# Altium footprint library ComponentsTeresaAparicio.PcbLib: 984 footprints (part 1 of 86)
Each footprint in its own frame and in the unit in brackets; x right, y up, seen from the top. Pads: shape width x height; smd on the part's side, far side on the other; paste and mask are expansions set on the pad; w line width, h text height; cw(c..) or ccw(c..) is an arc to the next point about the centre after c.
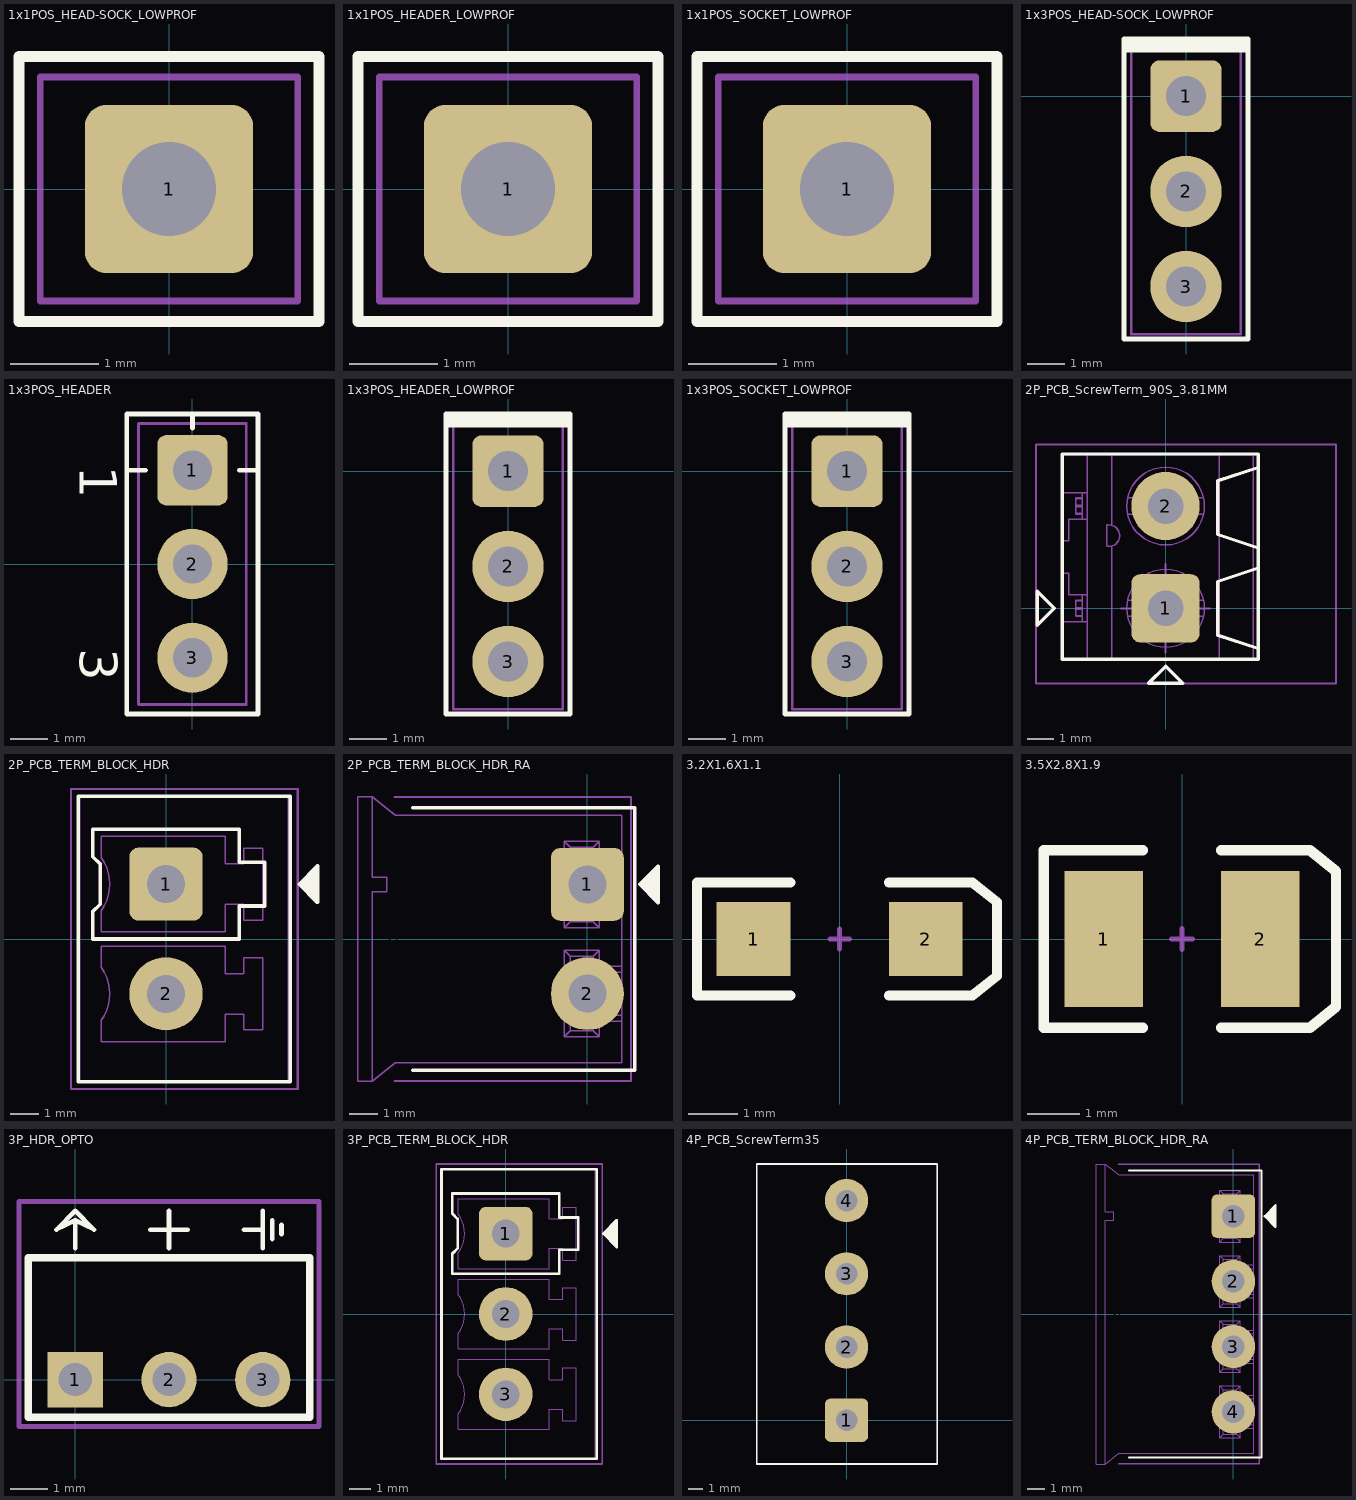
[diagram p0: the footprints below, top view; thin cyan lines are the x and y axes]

## 1x1POS_HEAD-SOCK_LOWPROF [mil] "Connector Socket with header, Single-row 1-position, 0.100\" pitch"
height 290
pads (1):
  rrect25% 75x75 hole 42: 1(0,0)
Top Overlay:
  lines w5: -66.93,-59.05 66.93,-59.05 66.93,59.06 -66.93,59.06 -66.93,-59.05
Mechanical 13:
  lines w3: -57.47,-49.99 57.49,-49.99 57.49,50.01 -57.47,50.01 -57.47,-49.99
3D body: height 165, standoff -125, extent -57.47,-50 57.49,50
3D body: height 408, standoff 23, extent -57.47,-50 57.49,50

## 1x1POS_HEADER_LOWPROF [mil] "Connector Header, Single-row 1-position, 0.100\" pitch"
height 267
pads (1):
  rrect25% 75x75 hole 42: 1(0,0)
Top Overlay:
  lines w5: -66.93,-59.06 66.93,-59.06 66.93,59.06 -66.93,59.06 -66.93,-59.06
Mechanical 13:
  lines w3: -57.47,-50 57.49,-50 57.49,50 -57.47,50 -57.47,-50
3D body: height 267, standoff -118, extent -57.47,-50 57.49,50

## 1x1POS_SOCKET_LOWPROF [mil] "Connector Socket, Single-row 1-position, 0.100\" pitch"
height 165
pads (1):
  rrect25% 75x75 hole 42: 1(0,0)
Top Overlay:
  lines w5: -66.93,-59.06 -66.93,59.06 66.93,59.06 66.93,-59.06 -66.93,-59.06
Mechanical 13:
  lines w3: -57.47,-50 -57.47,50 57.49,50 57.49,-50 -57.47,-50
3D body: height 165, standoff -125, extent -57.47,-50 57.49,50

## 1x3POS_HEAD-SOCK_LOWPROF [mil] "Connector Socket with header, Single-row 3-position, 0.100\" pitch"
height 290
pads (3):
  rrect25% 75x75 hole 42: 1(0,0)
  round 75 hole 42: 2(0,-100) 3(0,-200)
Top Overlay:
  lines w5: -65,48.19 65,48.19 ; -65,52.13 65,52.13 ; -65,56.06 65,56.06 ; -65,-255 -65,60 65,60 65,-255 -65,-255
Mechanical 13:
  lines w3: -57.47,-250 -57.47,50 57.49,50 57.49,-250 -57.47,-250
3D body: height 165, standoff -125, extent -57.47,-50 57.49,50
3D body: height 165, standoff -125, extent -57.47,-150 57.49,-50
3D body: height 165, standoff -125, extent -57.47,-250 57.49,-150
3D body: height 408, standoff 23, extent -57.48,-50 57.49,50
3D body: height 408, standoff 23, extent -57.48,-150 57.49,-50
3D body: height 408, standoff 23, extent -57.48,-250 57.49,-150

## 1x3POS_HEADER [mil] "Connector Header, Single-row 3-position, 0.100\" pitch"
height 235
pads (3):
  rrect25% 75x75 hole 42: 1(0,100)
  round 75 hole 42: 2(0,0) 3(0,-100)
Top Overlay:
  lines w5: -70,100 -50,100 ; 0,145 0,160 ; 50,100 70,100 ; -70,-160 70,-160 70,160 -70,160 -70,-160
  text "1" at -120,105 h40
  text "3" at -120,-90 h40
Mechanical 13:
  lines w3: -57.47,-150 57.49,-150 57.49,150 -57.47,150 -57.47,-150
3D body: height 335.04, standoff -144.88, extent -57.47,-150 57.49,150

## 1x3POS_HEADER_LOWPROF [mil] "Connector Header, Single-row 3-position, 0.100\" pitch"
height 267
pads (3):
  rrect25% 75x75 hole 42: 1(0,0)
  round 75 hole 42: 2(0,-100) 3(0,-200)
Top Overlay:
  lines w5: -65,48.19 65,48.19 ; -65,52.13 65,52.13 ; -65,56.06 65,56.06 ; -65,-255 65,-255 65,60 -65,60 -65,-255
Mechanical 13:
  lines w3: -57.47,-250 57.49,-250 57.49,50 -57.47,50 -57.47,-250
3D body: height 267, standoff -118, extent -57.47,-250 57.49,-150
3D body: height 267, standoff -118, extent -57.47,-150 57.49,-50
3D body: height 267, standoff -118, extent -57.47,-50 57.49,50

## 1x3POS_SOCKET_LOWPROF [mil] "Connector Socket, Single-row 3-position, 0.100\" pitch"
height 165
pads (3):
  rrect25% 75x75 hole 42: 1(0,0)
  round 75 hole 42: 2(0,-100) 3(0,-200)
Top Overlay:
  lines w5: -65,48.19 65,48.19 ; -65,52.13 65,52.13 ; -65,56.06 65,56.06 ; -65,-255 65,-255 65,60 -65,60 -65,-255
Mechanical 13:
  lines w3: -57.47,-250 57.49,-250 57.49,50 -57.47,50 -57.47,-250
3D body: height 165, standoff -125, extent -57.47,-250 57.49,-150
3D body: height 165, standoff -125, extent -57.47,-150 57.49,-50
3D body: height 165, standoff -125, extent -57.47,-50 57.49,50

## 2P_PCB_ScrewTerm_90S_3.81MM [mil] "TERM BLOCK 2POS SIDE ENT STACKABLE 3.81MM"
height 334.65
pads (2):
  rrect25% 100x100 hole 52: 1(0,0)
  round 100 hole 52: 2(0,150)
Top Overlay:
  lines w5: 135.83,-59.06 76.78,-39.37 76.78,39.37 135.83,59.06 ; 135.83,88.58 76.78,108.27 76.78,187.01 135.83,206.69 ; -188,-25 -163,0 -188,25 -188,-25 ; -151.57,-75 -151.57,226.38 135.83,226.38 135.83,-75 -151.57,-75 ; -25,-110 25,-110 0,-85 -25,-110
Mechanical 13:
  circle w1.97: c0,0 r57.09
  circle w1.97: c0,150 r57.09
  lines w1.97: -151.57,-19.69 -114.76,-19.69 -114.76,19.68 -141.73,19.68 -141.73,51.18 -151.57,51.18 ; -151.57,98.82 -141.73,98.82 -141.73,130.31 -114.76,130.31 -114.76,169.69 -151.57,169.69 ; -131.89,-10.91 -122.05,-10.91 ; -131.89,-1.06 -122.05,-1.06 ; -131.89,1.06 -122.05,1.06 ; -131.89,10.91 -122.05,10.91 ; -131.89,139.09 -122.05,139.09 ; -131.89,148.94 -122.05,148.94 ; -131.89,151.06 -122.05,151.06 ; -131.89,160.91 -122.05,160.91 ; -122.05,-19.69 -122.05,19.68 ; -122.05,-11.81 -131.89,-11.81 -131.89,11.81 -122.05,11.81 ; -122.05,130.31 -122.05,169.69 ; -122.05,138.19 -131.89,138.19 -131.89,161.81 -122.05,161.81 ; -114.56,-75 -114.56,225 ; -78.74,-75 -78.74,91.34 ; -78.74,121.65 -78.74,225 ; -55.85,-11.81 55.85,-11.81 ; -55.85,11.81 55.85,11.81 ; -55.85,138.19 55.85,138.19 ; -55.85,161.81 55.85,161.81 ; 78.74,-75 78.74,225 ; 128.89,-75 128.89,225 ; -151.57,-75 -151.57,225 135.83,225 135.83,-75 -151.57,-75 ; -85.91,90.75 -83.03,90.75 ccw(c-83.03,106.5) -83.03,122.24 -85.91,122.24 -85.91,90.75
Mechanical 14:
  lines w3: -65,0 65,0 ; 0,-65 0,65 ; -190,-110 -190,240 250,240 250,-110 -190,-110
3D body: height 334.65, standoff -137.8, extent -151.57,-75.19 135.83,224.81

## 2P_PCB_TERM_BLOCK_HDR [mil] "TERM BLOCK HDR 2POS 3.81MM"
height 362.2
pads (2):
  rrect25% 100x100 hole 52: 1(0,75)
  round 100 hole 52: 2(0,-75)
Top Overlay:
  region: 182,75 207,100 207,50
  lines w5: -120,-195.08 -120,195.08 ; -120,-195 170,-195 ; -120,195 170,195 ; 170,-195.08 170,195.08 ; -100,0 100,0 100,45 135,45 135,105 100,105 100,150 -100,150 -100,112.5 -90,102.5 -90,47.5 -100,37.5 -100,0 ; 182,75 207,100 207,50 182,75
Mechanical 13:
  circle w1.97: c0,-75 r43.31
  circle w1.97: c0,75 r43.31
  circle w1.97: c0,75 r35.43
  circle w1.97: c0,-75 r35.43
  lines w1.97: -118.11,-195.08 -118.11,195.08 167.32,195.08 167.32,-195.08 -118.11,-195.08 ; -88.58,-140.16 -88.58,-111.08 ccw(c-137.8,-75) -88.58,-38.92 -88.58,-9.84 80.71,-9.84 80.71,-47.44 106.3,-47.44 106.3,-25.79 131.89,-25.79 131.89,-124.21 106.3,-124.21 106.3,-102.56 80.71,-102.56 80.71,-140.16 -88.58,-140.16 ; -88.58,9.84 -88.58,38.92 ccw(c-137.8,75) -88.58,111.08 -88.58,140.16 80.71,140.16 80.71,102.56 106.3,102.56 106.3,124.21 131.89,124.21 131.89,25.79 106.3,25.79 106.3,47.44 80.71,47.44 80.71,9.84 -88.58,9.84 ; -15.75,-90.75 15.75,-90.75 15.75,-59.25 -15.75,-59.25 -15.75,-90.75 ; -15.75,59.25 15.75,59.25 15.75,90.75 -15.75,90.75 -15.75,59.25
Mechanical 14:
  lines w3: -130,-205 180,-205 180,205 -130,205 -130,-205
3D body: height 362.2, standoff -133.86, extent -118.1,-195.07 167.33,195.08

## 2P_PCB_TERM_BLOCK_HDR_RA [mil] "TERM BLOCK HDR 2POS 3.81MM RIGHT-ANGLE"
height 362.2
pads (3):
  round 40 on Mech14: 0(-265,0)
  rrect25% 100x100 hole 52: 1(0,75)
  round 100 hole 52: 2(0,-75)
Top Overlay:
  region: 72,75 97,100 97,50
  lines w5: -240,-180 65,-180 65,180 -240,180 ; 72,75 97,100 97,50 72,75
Mechanical 13:
  lines w1.97: 47.24,-112.8 7.87,-112.8 ; 47.24,-104.53 16.14,-104.53 ; 47.24,-45.47 16.14,-45.47 ; 47.24,-37.2 7.87,-37.2 ; 47.24,37.2 7.87,37.2 ; 47.24,45.47 16.14,45.47 ; 47.24,104.53 16.14,104.53 ; 47.24,112.8 7.87,112.8 ; -295.28,-195.08 -263.78,-169.88 47.24,-169.88 47.24,169.88 -263.78,169.88 -295.28,195.08 ; -295.28,-195.08 -314.96,-195.08 -314.96,195.08 -295.28,195.08 ; -295.28,-195.08 -295.28,65.16 -275.59,65.16 -275.59,84.84 -295.28,84.84 -295.28,195.08 ; -31.89,-134.45 -23.62,-126.18 ; -31.89,-134.45 16.14,-134.45 ; -31.89,-134.45 -31.89,-15.55 ; -31.89,-15.55 -23.62,-23.82 ; -31.89,-15.55 16.14,-15.55 ; -31.89,15.55 -23.62,23.82 ; -31.89,15.55 16.14,15.55 ; -31.89,15.55 -31.89,134.45 ; -31.89,134.45 -23.62,126.18 ; -31.89,134.45 16.14,134.45 ; -23.62,-126.18 7.87,-126.18 ; -23.62,-126.18 -23.62,-23.82 ; -23.62,-23.82 7.87,-23.82 ; -23.62,23.82 7.87,23.82 ; -23.62,23.82 -23.62,126.18 ; -23.62,126.18 7.87,126.18 ; 7.87,-126.18 7.87,-112.8 ; 7.87,-126.18 16.14,-134.45 ; 7.87,-112.8 cw(c16.14,-112.8) 16.14,-104.53 ; 7.87,-37.2 ccw(c16.14,-37.2) 16.14,-45.47 ; 7.87,-37.2 7.87,-23.82 ; 7.87,-23.82 16.14,-15.55 ; 7.87,23.82 7.87,37.2 ; 7.87,23.82 16.14,15.55 ; 7.87,37.2 cw(c16.14,37.2) 16.14,45.47 ; 7.87,112.8 ccw(c16.14,112.8) 16.14,104.53 ; 7.87,112.8 7.87,126.18 ; 7.87,126.18 16.14,134.45 ; 16.14,-134.45 16.14,-104.53 ; 16.14,-45.47 16.14,-15.55 ; 16.14,15.55 16.14,45.47 ; 16.14,104.53 16.14,134.45
Mechanical 14:
  lines w3: -265,-195 60,-195 60,195 -265,195
3D body: height 291.34, standoff -129.92, extent -314.95,-195.07 47.25,195.08

## 3.2X1.6X1.1 [mm] "SMT LED; 2 Flat Leads"
height 1.2
pads (2):
  rect 1.5x1.5 smd: 1(-1.75,0) 2(1.75,0)
Top Overlay:
  lines w0.2: -1,-1.15 -2.9,-1.15 -2.9,1.15 -1,1.15 ; 1,-1.15 2.7,-1.15 3.2,-0.75 3.2,0.75 2.7,1.15 1,1.15
Mechanical 1:
  lines w0.1: -0.2,0 0.2,0 ; 0,-0.2 0,0.2

## 3.5X2.8X1.9 [mm] "SM LED; 2 C-Bend Leads; Body 3.5 x 2.8 x 1.9 mm, inc leads (LxWxH typ)"
height 1.9
pads (2):
  rect 1.5x2.6 smd: 1(-1.5,0) 2(1.5,0)
Top Overlay:
  lines w0.2: -0.75,-1.7 -2.65,-1.7 -2.65,1.7 -0.75,1.7 ; 0.75,-1.7 2.45,-1.7 2.95,-1.3 2.95,1.3 2.45,1.7 0.75,1.7
Mechanical 1:
  lines w0.1: -0.2,0 0.2,0 ; 0,-0.2 0,0.2

## 3P_HDR_OPTO [mm] "Connector; screwterm; 3 Position"
height 10
pads (3):
  rect 1.5x1.5 hole 0.9: 1(0,0)
  round 1.5 hole 0.9: 2(2.54,0) 3(5.08,0)
Top Overlay:
  lines w0.127: 0,3.556 0,4.318 ; 2.032,4.064 3.048,4.064 ; 2.54,3.556 2.54,4.572 ; 4.572,4.064 5.08,4.064 5.08,4.572 5.08,3.556 ; 5.334,3.81 5.334,4.318 ; 5.588,3.937 5.588,4.191 ; 0,4.318 0.508,4.064 0,4.572 -0.508,4.064 0,4.318
  lines w0.2: -1.27,-1.016 6.35,-1.016 6.35,3.302 -1.27,3.302 -1.27,-1.016
Mechanical 14:
  lines w0.127: -1.524,-1.27 6.604,-1.27 6.604,4.826 -1.524,4.826 -1.524,-1.27
3D body: height 6.48, standoff -3.56, extent -1.27,-0.317 6.35,10.732

## 3P_PCB_TERM_BLOCK_HDR [mil] "TERM BLOCK HDR 3POS 3.81MM"
height 362.2
pads (3):
  rrect25% 100x100 hole 52: 1(0,150)
  round 100 hole 52: 2(0,0) 3(0,-150)
Top Overlay:
  region: 182,150 207,175 207,125
  lines w5: -120,-270 -120,270 170,270 170,-270 -120,-270 ; -100,75 -100,112.5 -90,122.5 -90,177.5 -100,187.5 -100,225 100,225 100,180 135,180 135,120 100,120 100,75 -100,75 ; 182,150 207,125 207,175 182,150
Mechanical 13:
  circle w1.97: c0,-150 r43.31
  circle w1.97: c0,0 r43.31
  circle w1.97: c0,150 r43.31
  circle w1.97: c0,0 r35.43
  circle w1.97: c0,-150 r35.43
  circle w1.97: c0,150 r35.43
  lines w1.97: -118.11,-270.08 167.32,-270.08 167.32,270.08 -118.11,270.08 -118.11,-270.08 ; -88.58,-215.16 80.71,-215.16 80.71,-177.56 106.3,-177.56 106.3,-199.21 131.89,-199.21 131.89,-100.79 106.3,-100.79 106.3,-122.44 80.71,-122.44 80.71,-84.84 -88.58,-84.84 -88.58,-113.92 cw(c-137.8,-150) -88.58,-186.08 -88.58,-215.16 ; -88.58,-65.16 -88.58,-36.08 ccw(c-137.8,0) -88.58,36.08 -88.58,65.16 80.71,65.16 80.71,27.56 106.3,27.56 106.3,49.21 131.89,49.21 131.89,-49.21 106.3,-49.21 106.3,-27.56 80.71,-27.56 80.71,-65.16 -88.58,-65.16 ; -88.58,84.84 80.71,84.84 80.71,122.44 106.3,122.44 106.3,100.79 131.89,100.79 131.89,199.21 106.3,199.21 106.3,177.56 80.71,177.56 80.71,215.16 -88.58,215.16 -88.58,186.08 cw(c-137.8,150) -88.58,113.92 -88.58,84.84 ; -15.75,-165.75 -15.75,-134.25 15.75,-134.25 15.75,-165.75 -15.75,-165.75 ; -15.75,-15.75 -15.75,15.75 15.75,15.75 15.75,-15.75 -15.75,-15.75 ; -15.75,134.25 15.75,134.25 15.75,165.75 -15.75,165.75 -15.75,134.25
Mechanical 14:
  lines w3: -130,-280 -130,280 180,280 180,-280 -130,-280
3D body: height 362.2, standoff -133.86, extent -118.1,-270.08 167.33,270.08

## 4P_PCB_ScrewTerm35 [mm] "TERM BLOCK 4POS 35° ENT 5.08MM"
height 15
pads (4):
  rrect25% 3x3 hole 1.5: 1(0,0)
  round 3 hole 1.5: 2(0,5.08) 3(0,10.16) 4(0,15.24)
Top Overlay:
  lines w0.127: -6.231,-3.04 -6.231,17.78 6.289,17.78 6.289,-3.04 -6.231,-3.04
Mechanical 13:
  lines w0.076: -6.231,-3.04 6.289,-3.04 6.289,17.78 -6.231,17.78 -6.231,-3.04
3D body: height 15.04, standoff -3.76, extent -6.231,-3.04 6.289,17.78

## 4P_PCB_TERM_BLOCK_HDR_RA [mil] "TERM BLOCK HDR 4POS 3.81MM RIGHT-ANGLE"
height 362.2
pads (5):
  round 40 on Mech14: 0(-265,0)
  rrect25% 100x100 hole 52: 1(0,225)
  round 100 hole 52: 2(0,75) 3(0,-75) 4(0,-225)
Top Overlay:
  region: 72,225 97,250 97,200
  lines w5: -240,-330 65,-330 65,330 -240,330 ; 72,225 97,200 97,250 72,225
Mechanical 13:
  lines w1.97: 47.24,-262.8 7.87,-262.8 ; 47.24,-254.53 16.14,-254.53 ; 47.24,-195.47 16.14,-195.47 ; 47.24,-187.2 7.87,-187.2 ; 47.24,-112.8 7.87,-112.8 ; 47.24,-104.53 16.14,-104.53 ; 47.24,-45.47 16.14,-45.47 ; 47.24,-37.2 7.87,-37.2 ; 47.24,37.2 7.87,37.2 ; 47.24,45.47 16.14,45.47 ; 47.24,104.53 16.14,104.53 ; 47.24,112.8 7.87,112.8 ; 47.24,187.2 7.87,187.2 ; 47.24,195.47 16.14,195.47 ; 47.24,254.53 16.14,254.53 ; 47.24,262.8 7.87,262.8 ; -295.28,-345.08 -263.78,-319.88 47.24,-319.88 47.24,319.88 -263.78,319.88 -295.28,345.08 ; -295.28,-345.08 -295.28,215.16 -275.59,215.16 -275.59,234.84 -295.28,234.84 -295.28,345.08 ; -295.28,-345.08 -314.96,-345.08 -314.96,345.08 -295.28,345.08 ; -31.89,-284.45 -31.89,-165.55 ; -31.89,-284.45 -23.62,-276.18 ; -31.89,-284.45 16.14,-284.45 ; -31.89,-165.55 -23.62,-173.82 ; -31.89,-165.55 16.14,-165.55 ; -31.89,-134.45 -23.62,-126.18 ; -31.89,-134.45 16.14,-134.45 ; -31.89,-134.45 -31.89,-15.55 ; -31.89,-15.55 -23.62,-23.82 ; -31.89,-15.55 16.14,-15.55 ; -31.89,15.55 -23.62,23.82 ; -31.89,15.55 16.14,15.55 ; -31.89,15.55 -31.89,134.45 ; -31.89,134.45 -23.62,126.18 ; -31.89,134.45 16.14,134.45 ; -31.89,165.55 -23.62,173.82 ; -31.89,165.55 16.14,165.55 ; -31.89,165.55 -31.89,284.45 ; -31.89,284.45 -23.62,276.18 ; -31.89,284.45 16.14,284.45 ; -23.62,-276.18 -23.62,-173.82 ; -23.62,-276.18 7.87,-276.18 ; -23.62,-173.82 7.87,-173.82 ; -23.62,-126.18 7.87,-126.18 ; -23.62,-126.18 -23.62,-23.82 ; -23.62,-23.82 7.87,-23.82 ; -23.62,23.82 -23.62,126.18 ; -23.62,23.82 7.87,23.82 ; -23.62,126.18 7.87,126.18 ; -23.62,173.82 -23.62,276.18 ; -23.62,173.82 7.87,173.82 ; -23.62,276.18 7.87,276.18 ; 7.87,-276.18 7.87,-262.8 ; 7.87,-276.18 16.14,-284.45 ; 7.87,-262.8 cw(c16.14,-262.8) 16.14,-254.53 ; 7.87,-187.2 ccw(c16.14,-187.2) 16.14,-195.47 ; 7.87,-187.2 7.87,-173.82 ; 7.87,-173.82 16.14,-165.55 ; 7.87,-126.18 7.87,-112.8 ; 7.87,-126.18 16.14,-134.45 ; 7.87,-112.8 cw(c16.14,-112.8) 16.14,-104.53 ; 7.87,-37.2 ccw(c16.14,-37.2) 16.14,-45.47 ; 7.87,-37.2 7.87,-23.82 ; 7.87,-23.82 16.14,-15.55 ; 7.87,23.82 7.87,37.2 ; 7.87,23.82 16.14,15.55 ; 7.87,37.2 cw(c16.14,37.2) 16.14,45.47 ; 7.87,112.8 ccw(c16.14,112.8) 16.14,104.53 ; 7.87,112.8 7.87,126.18 ; 7.87,126.18 16.14,134.45 ; 7.87,173.82 7.87,187.2 ; 7.87,173.82 16.14,165.55 ; 7.87,187.2 cw(c16.14,187.2) 16.14,195.47 ; 7.87,262.8 ccw(c16.14,262.8) 16.14,254.53 ; 7.87,262.8 7.87,276.18 ; 7.87,276.18 16.14,284.45 ; 16.14,-284.45 16.14,-254.53 ; 16.14,-195.47 16.14,-165.55 ; 16.14,-134.45 16.14,-104.53 ; 16.14,-45.47 16.14,-15.55 ; 16.14,15.55 16.14,45.47 ; 16.14,104.53 16.14,134.45 ; 16.14,165.55 16.14,195.47 ; 16.14,254.53 16.14,284.45
Mechanical 14:
  lines w3: -265,-345 60,-345 60,345 -265,345
3D body: height 291.34, standoff -129.92, extent -314.95,-345.07 47.25,345.08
